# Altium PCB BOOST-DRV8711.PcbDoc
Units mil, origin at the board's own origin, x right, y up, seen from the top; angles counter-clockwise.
Board outline 2000 x 1750 mil, 2 copper layers (Top Layer, Bottom Layer), stack 64.8 mil thick; 30 components, 42 nets, 138 pads, 203 vias.
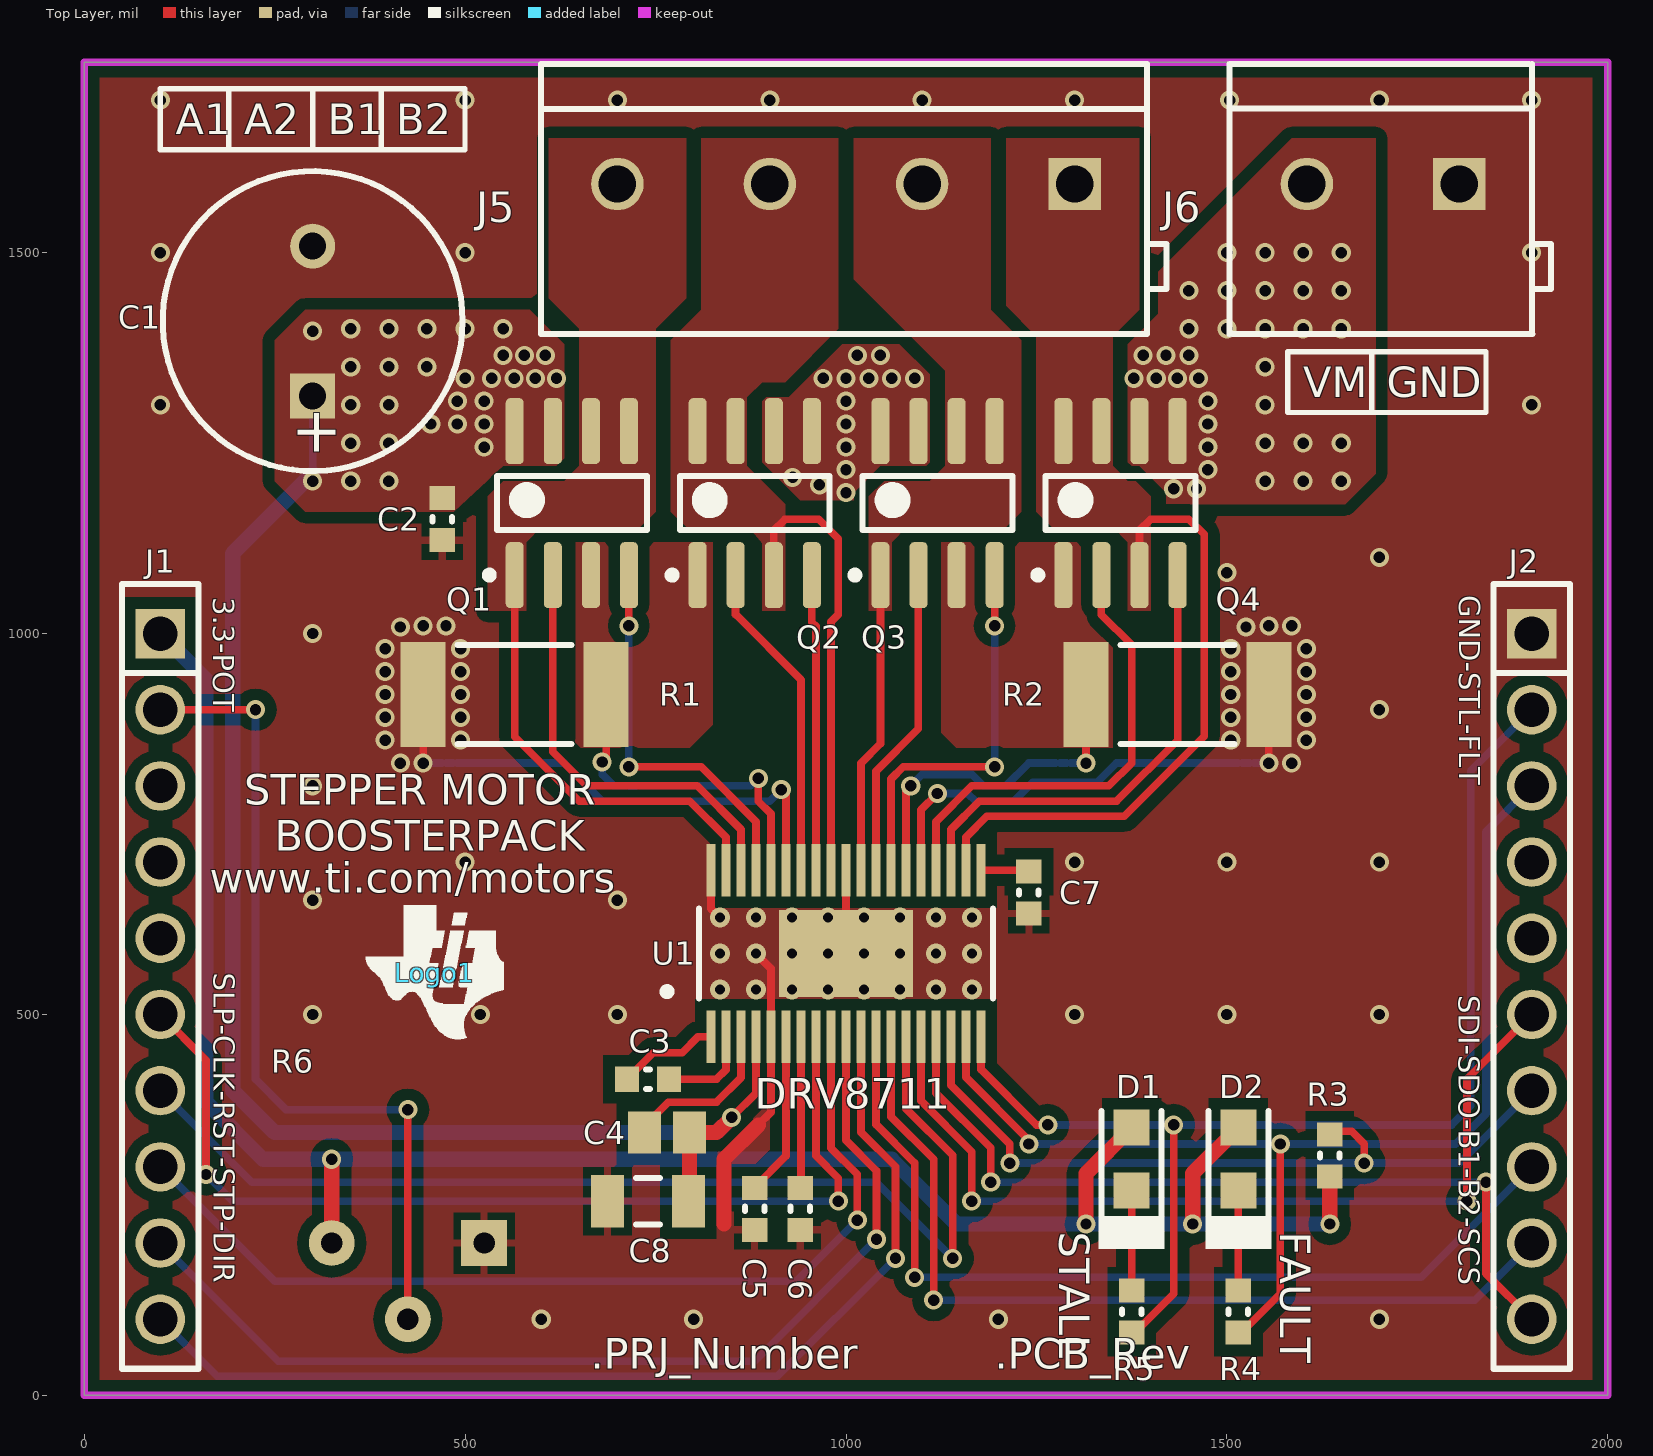
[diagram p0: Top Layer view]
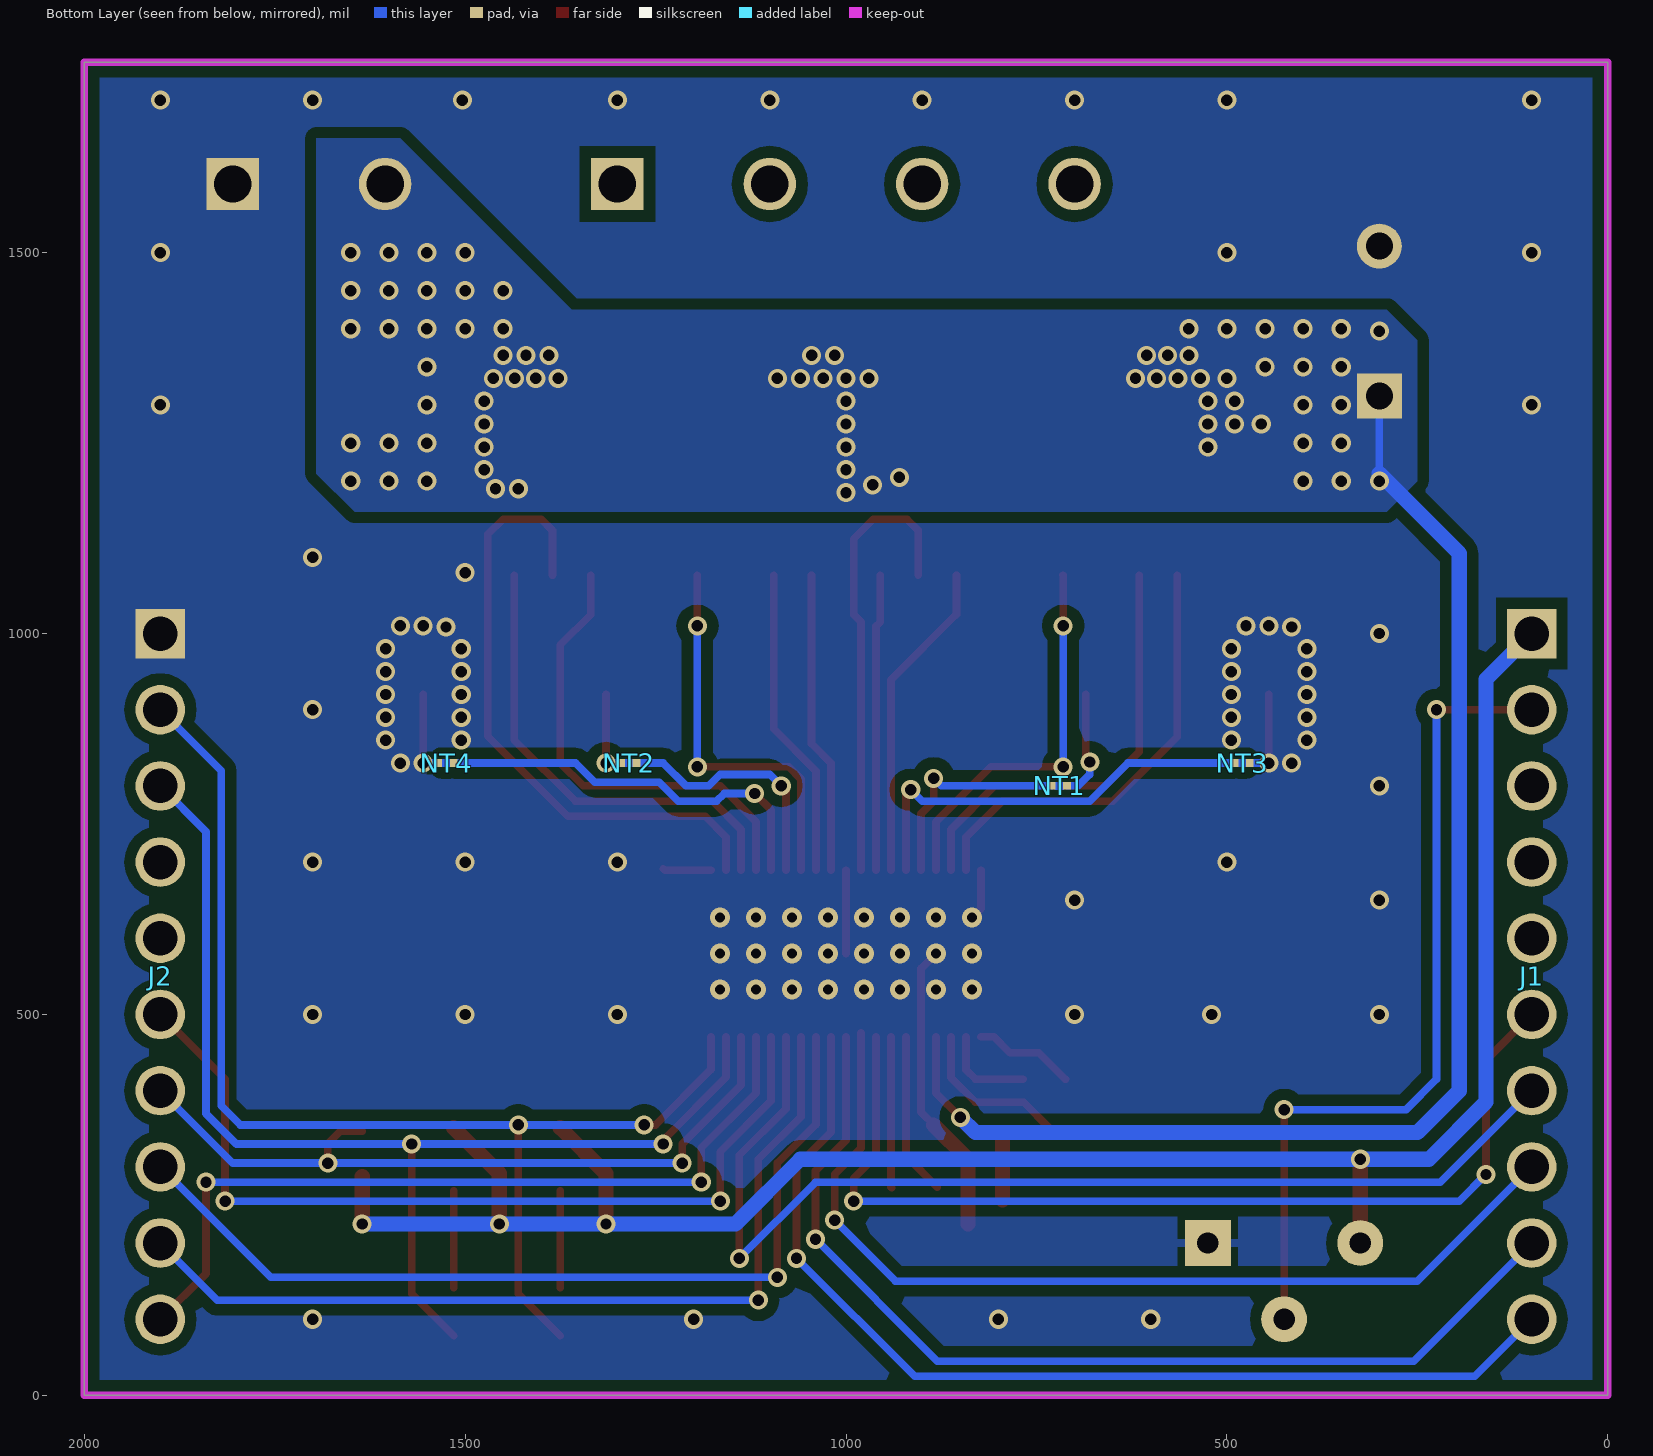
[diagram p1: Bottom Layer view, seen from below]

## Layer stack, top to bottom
Top Layer: signal copper 2.8
Dielectric: core 59.2, FR-4, Dk 4.8
Bottom Layer: signal copper 2.8

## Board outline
0,0 2000,0 2000,1750 0,1750

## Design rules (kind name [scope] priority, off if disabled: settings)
AcuteAngle [All] p1: minimum=4.50000000000000E+0001 checktracksonly=FALSE
AssemblyTestPointUsage [All] p1: valid=2
Clearance Clearance_BoardEdge_MountingHoles [OnCopper and InComponentClass('Mounting Holes') vs IsKeepOut] p1: gap=15
Clearance Clearance_BoardEdge_Poly [OnCopper and InPoly vs IsKeepOut] p2: gap=15
Clearance Clearance_BoardEdge [OnCopper and Not InComponentClass('Logo') and not InComponentClass('FiducialMark') and not InRegion(1000,500,4000,800) and Not IsKeepout vs IsKeepOut] p3: gap=15
Clearance Clearance_Poly [InPolygon] p4: gap=15
Clearance [All] p5: gap=7
ComponentClearance ComponentClearance_Logo [InComponentClass(Logo)] p1: gap=10 collisioncheckmode=3 verticalgap=10 showdistances=FALSE
ComponentClearance ComponentClearance_ScrewToNut [(HasFootprint('NY PMS 440 0025 PH')) vs (HasFootprint('Keystone_1902C'))] p2: gap=5 collisioncheckmode=3 verticalgap=10 showdistances=FALSE
ComponentClearance ComponentClearance_MountingHoles [InComponentClass('Mounting Holes')] p3: gap=250 collisioncheckmode=3 verticalgap=100000 showdistances=FALSE
ComponentClearance ComponentClearance_SmallPassives [HasFootprint('0201*') or HasFootprint('0402*') or HasFootprint('0508') or HasFootprint('0603*') or HasFootprint('0612') or HasFootprint('0805*') or HasFootprint('0815*') or HasFootprint('0830*') or HasFootprint('1206*') or HasFootprint('1210*') or HasFootprint('1808*') or HasFootprint('1812*') or HasFootprint('1825*') or HasFootprint('2010*') or HasFootprint('2220*') or HasFootprint('2225*') or HasFootprint('2512*') or HasFootprint('2728*') or HasFootprint('3518*') vs HasFootprint('0201*') or HasFootprint('0402*') or HasFootprint('0508') or HasFootprint('0603*') or HasFootprint('0612') or HasFootprint('0805*') or HasFootprint('0815*') or HasFootprint('0830*') or HasFootprint('1206*') or HasFootprint('1210*') or HasFootprint('1808*') or HasFootprint('1812*') or HasFootprint('1825*') or HasFootprint('2010*') or HasFootprint('2220*') or HasFootprint('2225*') or HasFootprint('2512*') or HasFootprint('2728*') or HasFootprint('3518*')] p4: gap=10 collisioncheckmode=3 verticalgap=10 showdistances=FALSE
ComponentClearance ComponentClearance_THtoSMT [IsThruComponent vs IsSMTComponent] p5: gap=10 collisioncheckmode=3 verticalgap=100000 showdistances=FALSE
ComponentClearance ComponentClearance_THtoTH [IsThruComponent vs IsThruComponent] p6: gap=0 collisioncheckmode=3 verticalgap=0 showdistances=FALSE
ComponentClearance [All] p7: gap=10 collisioncheckmode=3 verticalgap=10 showdistances=FALSE
DiffPairsRouting [All] p1: maxlimit=100 minlimit=10 mostfreqgap=10 maxuncoupledlength=1000
FabricationTestPointUsage TestPointUsage [All] p1: valid=2 allowmultiple=FALSE
FabricationTestpoint Testpoint [All] p1: side=3 testpointundercomponent=TRUE minsize=40 maxsize=100 preferedsize=60 minholesize=0 maxholesize=40 preferedholesize=32 testpointgrid=1 allowsidetop=TRUE allowsidebottom=TRUE usegrid=TRUE gridtolerance=0.01
FanoutControl Fanout_LCC [IsLCC] p1: bgadir=Out bgaviamode=Centered fanoutstyle=Auto fanoutdirection=Alternating viagrid=1 // Fanout_LCC (Default Rule)
FanoutControl Fanout_BGA [IsBGA] p2: bgadir=Out bgaviamode=Centered fanoutstyle=Auto fanoutdirection=Alternating viagrid=1 // Fanout_BGA (Default Rule)
FanoutControl Fanout_Default [All] p4: bgadir=Out bgaviamode=Centered fanoutstyle=Auto fanoutdirection=Alternating viagrid=1 // Fanout_Default (Default Rule)
FanoutControl Fanout_Small [(CompPinCount < 5)] p5: bgadir=Out bgaviamode=Centered fanoutstyle=Auto fanoutdirection=OutThenIn viagrid=1 // Fanout_Small (Default Rule)
HoleSize [All] p1: absolutevalues=TRUE maxlimit=251 minlimit=8 maxpercent=80.000 minpercent=20.000
MinimumAnnularRing [All] p1: minimumring=5
MinimumSolderMaskSliver MinimumSolderMaskSliver_Logo [InComponentClass('Logo') vs InComponentClass('Logo')] p1: minsoldermaskwidth=0.7
MinimumSolderMaskSliver [All] p2: minsoldermaskwidth=3
PlaneClearance [All] p1: clearance=15
PlaneConnect [All] p1: planeconnectstyle=Relief reliefexpansion=10 reliefentries=4 reliefconductorwidth=10 reliefairgap=10
PolygonConnect PolygonConnect_1 [IsNamedPolygon('GND_TOP') or IsNamedPolygon('GND_BOT') vs Not (InComponent('U1') or InComponent('J2') or InComponent('J3') or InComponent('J5') or InComponent('C1') or InComponent('R1') or InComponent('R2') or IsStitchingVia or IsVia)] p1: connectstyle=Relief reliefconductorwidth=10 reliefentries=4 polygonreliefangle="90 Angle" airgapwidth=10
PolygonConnect [All] p2: connectstyle=Direct reliefconductorwidth=10 reliefentries=4 polygonreliefangle="90 Angle" airgapwidth=10
RoutingVias [All] p1: holewidth=15 width=25 viastyle="Through Hole" minholewidth=8 minwidth=20 maxholewidth=40 maxwidth=65
SMDToCorner [All] p1: distance=30000
SilkToSilkClearance [All] p1: silktosilkclearance=5
SilkscreenOverComponentPads [All] p1: minsilkscreentomaskgap=5
SolderMaskExpansion [All] p1: expansion=3
Width [All] p1: maxlimit=100 minlimit=6 preferedwidth=10 checkconnectedcopper=TRUE
13 further rules are at their usual default settings.

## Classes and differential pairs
component class Logo: Logo1

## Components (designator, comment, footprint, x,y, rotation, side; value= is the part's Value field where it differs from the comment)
C1 "ECA-2AM101" CAPPR5-10X20 300,1410 r90 top
C2 "C1608X7R2A103K" 0603L 470,1150 r270 top
C3 "GRM188R72A104KA35D" 0603L 740,415 r0 top
C4 "CL21B105KBFNNNE" 0805L 765,345 r0 top
C5 "C1608X7R1E104K" 0603L 880,245 r270 top
C6 "C1608X7R1C105K" 0603L 940,245 r270 top
C7 "C0603C102K4RACTU" 0603L 1240,660 r270 top
C8 "HMK316B7105KL-T" 1206L 740,255 r180 top
D1 "LTST-C170KRKT" LED_LTST-C170 1375,310 r270 top
D2 "LTST-C170KRKT" LED_LTST-C170 1515,310 r270 top
J1 "CRD-081413-B-T" CONN_SSW-110-23-F-S 100,1000 r90 bottom
J2 "CRD-081413-B-T" CONN_SSW-110-23-F-S 1900,1000 r90 bottom
J5 "OSTTA024163" CONN_ED120-2DS 1705,1590 r90 top
J6 "OSTTA044163" CONN_ED120_4DS 1000,1590 r270 top
Logo1 "Texas Instruments" TI_Symbol_Overlay_Small 460,555 r0 top
NT1 "Net-Tie" Net-Tie_10mil 720,800 r180 bottom net-tie
NT2 "Net-Tie" Net-Tie_10mil 1285,830 r0 bottom net-tie
NT3 "Net-Tie" Net-Tie_10mil 480,830 r180 bottom net-tie
NT4 "Net-Tie" Net-Tie_10mil 1525,830 r0 bottom net-tie
Q1 "CSD88537ND" SO-8 640.23,1171.12 r90 top
Q2 "CSD88537ND" SO-8 880.23,1171.12 r90 top
Q3 "CSD88537ND" SO-8 1120.23,1171.12 r90 top
Q4 "CSD88537ND" SO-8 1360.23,1171.12 r90 top
R1 "CRA2512-FZ-R050ELF" 2512M 565,920 r0 top
R2 "CRA2512-FZ-R050ELF" 2512M 1435,920 r180 top
R3 "CRCW06033K30JNEA" 0603L 1635,315 r270 top
R4 "CRCW0603330RJNEA" 0603L 1515,110 r270 top
R5 "CRCW0603330RJNEA" 0603L 1375,110 r90 top
R6 "3386P-104TLF-ND" POT_3386P 425,200 r90 top
U1 "DRV8711DCP" R-PDSO-G38 1000,580 r90 top

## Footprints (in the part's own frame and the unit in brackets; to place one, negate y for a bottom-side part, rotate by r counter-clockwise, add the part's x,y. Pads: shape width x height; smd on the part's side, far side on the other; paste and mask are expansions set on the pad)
0603L [mm] "0603 from SM-752 data"
  rect 0.8x0.85 smd: 1(-0.7,0) 2(0.7,0)
  silkscreen extent -0.07,-0.33 0.07,0.33, body extent -0.87,-0.47 0.87,0.47, height 0.85
0805L [mm] "0805 from SM-752 data"
  rect 1.1x1.4 smd: 1(-0.75,0) 2(0.75,0)
  body extent -1.1,-0.72 1.1,0.72, height 1.1
1206L [mm] "1206 from SM-752 data"
  rect 1.1x1.75 smd: 1(-1.35,0) 2(1.35,0)
  silkscreen extent -0.4,-0.77 0.4,0.77, body extent -1.7,-0.9 1.7,0.9, height 1.35
2512M [mm] "Chip Resistor, Body 6.3x3.2mm, IPC Low Density"
  rect 1.5x3.5 smd: 1(-3.05,0) 2(3.05,0)
  silkscreen extent -1.9,-1.65 1.9,1.65, body extent -3.22,-1.67 3.22,1.67, height 0.71
CAPPR5-10X20 [mm] "Capacitor, Electrolytic, Radial; Body 10 x 20 mm (Dia.xH typ); Pin Spacing 5 mm (typ)"
  rect 1.5x1.5 hole 0.9: 1(-2.5,0)
  round 1.5 hole 0.9: 2(2.5,0)
  silkscreen extent -5,-5 5,5, body extent -5.01,-5.01 5.01,5.01, height 22
CONN_ED120-2DS [mm] "ONSHORE"
  rect 1.75x1.75 hole 1.25: 1(0,-2.54)
  round 1.75 hole 1.25: 2(0,2.54)
  silkscreen extent -5,-5.6 4,5.12, body extent -5,-5.6 4.15,5.12, height 13.1
CONN_ED120_4DS [mm] "ONSHORE"
  rect 1.75x1.75 hole 1.25: 1(0,7.62)
  round 1.75 hole 1.25: 2(0,2.54) 3(0,-2.54) 4(0,-7.62)
  silkscreen extent -4,-10.16 5,10.68, body extent -4.13,-10.01 5.05,10.68, height 13.1
CONN_SSW-110-23-F-S [mm] "SAMTEC"
  rect 1.65x1.65 hole 1.15: 1(0,0)
  round 1.65 hole 1.15: 2(-2.54,0) 3(-5.08,0) 4(-7.62,0) 5(-10.16,0) 6(-12.7,0) 7(-15.24,0) 8(-17.78,0) 9(-20.32,0) 10(-22.86,0)
  body extent -24.43,-1.27 1.57,1.27, height 8.59
LED_LTST-C170 [mm] "LITE-ON"
  rect 1.2x1.2 smd: 1(-1.05,0) 2(1.05,0)
  silkscreen extent -1.6,-1.1 3,1.1, body extent -1.05,-0.67 1.05,0.67, height 1.1
Net-Tie_10mil [mil] "10mil net tie, no solder mask opening, no solder paste"
  rect 10x10 smd paste-5 mask-5: 1(-10,0) 2(10,0)
  Top Layer region: -6,5 6,5 6,-5 -6,-5
POT_3386P [mil]
  rect 60x60 hole 28: 1(0,-100)
  round 60 hole 28: 2(-100,0) 3(0,100)
R-PDSO-G38 [mm] "PowerPAD Plastic Small-Outline Package"
  rect 2.9x4.48 smd: 0(0,0)
  rect 1.75x0.3 smd mask+0.05: 1(-2.775,4.5) 2(-2.775,4) 3(-2.775,3.5) 4(-2.775,3) 5(-2.775,2.5) 6(-2.775,2) 7(-2.775,1.5) 8(-2.775,1) 9(-2.775,0.5) 10(-2.775,0) 11(-2.775,-0.5) 12(-2.775,-1) 13(-2.775,-1.5) 14(-2.775,-2) 15(-2.775,-2.5) 16(-2.775,-3) 17(-2.775,-3.5) 18(-2.775,-4) 19(-2.775,-4.5) 20(2.775,-4.5) 21(2.775,-4) 22(2.775,-3.5) 23(2.775,-3) 24(2.775,-2.5) 25(2.775,-2) 26(2.775,-1.5) 27(2.775,-1) 28(2.775,-0.5) 29(2.775,0) 30(2.775,0.5) 31(2.775,1) 32(2.775,1.5) 33(2.775,2) 34(2.775,2.5) 35(2.775,3) 36(2.775,3.5) 37(2.775,4) 38(2.775,4.5)
  silkscreen extent -1.5,-4.9 1.5,6.09, body extent -2.25,-4.9 2.25,4.9, height 1.2
SO-8 [mm] "SOIC, 8-Leads, Body 5.0x4.0mm (max), Pitch 1.27mm, IPC Medium Density"
  rrect50% 2.2x0.6 smd: 1(-2.4,1.905) 2(-2.4,0.635) 3(-2.4,-0.635) 4(-2.4,-1.905) 5(2.4,-1.905) 6(2.4,-0.635) 7(2.4,0.635) 8(2.4,1.905)
  silkscreen extent -2.52,-2.5 0.9,2.88, body extent -3,-2.45 3,2.45, height 1.59
TI_Symbol_Overlay_Small [mil]
  silkscreen extent -90,-88 91,88

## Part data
C1: library part EEV-FK2A101M, "CAP ALUM 100UF 100V 20% RADIAL"
C2: "CAP, CERM, 0.01uF, 100V, +/-10%, X7R, 0603"
C3: "CAP, CERM, 0.1uF, 100V, +/-10%, X7R, 0603"
C4: library part GRM21BR71H105KA12L, "CAP CER 1UF 50V 10% X7R 0805"
C5: "CAP, CERM, 0.1uF, 25V, +/-10%, X7R, 0603"
C6: "CAP, CERM, 1uF, 16V, +/-10%, X7R, 0603"
C7: library part GRM188R71C102KA01D, "CAP, CERM, 1000pF, 16V, +/-10%, X7R, 0603"
C8: library part GRM31CR72A105KA01L, "CAP CER 1UF 100V 10% X7R 1206"
D1 D2: "LED, Red, SMD"
J1 J2: library part SSW-110-23-F-S, "Connector, Receptacle, 100mil, 10x1, Gold plated, TH"
J5: library part ED120/2DS, "TERMINAL BLOCK 5.08MM VERT 2POS, TH"
J6: library part ED120/4DS, "Terminal Block, 4x1, 5.08mm, TH"
Logo1: library part TI_Logo, "Texas Instrument Corporate Signature"
NT1 NT2 NT3 NT4: "Single point connection between nets."
Q1 Q2 Q3 Q4: "Dual 60-V N-Channel NexFET™ Power MOSFETs"
R1 R2: "RES, 0.05 ohm, 1%, 3W, 2512"
R3: "RES, 3.3k ohm, 5%, 0.1W, 0603"
R4 R5: "RES, 330 ohm, 5%, 0.1W, 0603"
R6: library part POT_3386P, "TRIMMER 100K OHM 0.5W PC PIN"
U1: "Stepper Motor Pre-Driver with On-Chip 1/256 Micro-Stepping Indexer and Stall Detect"

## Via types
v1: diameter 25, hole 15, Top Layer to Bottom Layer, tented both sides, 179 vias
v2: diameter 26, hole 13, Top Layer to Bottom Layer, tented top, 24 vias

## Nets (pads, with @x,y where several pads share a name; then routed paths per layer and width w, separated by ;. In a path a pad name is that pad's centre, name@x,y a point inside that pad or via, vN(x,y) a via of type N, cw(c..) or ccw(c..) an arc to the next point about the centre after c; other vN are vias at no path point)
3.3V: D1.1 D2.1 J1.1 R3.2 R6.3 | length 2656
  Top Layer w20: R6.3 v1(325,310) ; v1(1315,225) 1315,291.34 D1.1 ; v1(1455,225) 1455,291.34 D2.1 ; v1(1635,225) R3.2
  Bottom Layer w20: J1.1 160,940 160,385 235,310 1060,310 1145,225 v1(1455,225) v1(1635,225)
A1HS: Q1.2 U1.36 | length 574.5
  Top Layer w10: Q1.2@615,1076.4 615,845 660,800 805,800 862.2,742.8 U1.36
A1LS: Q1.4 U1.35 | length 512.3
  Top Layer w10: v1(715,825) 810,825 881.89,753.11 U1.35 ; v1(715,1010) 715,1076.4 Q1.4
  Bottom Layer w10: v1(715,825) v1(715,1010)
A2HS: Q2.4 U1.31 | length 389.6
  Top Layer w10: Q2.4 955.23,1014.77 960.63,1009.37 U1.31
A2LS: Q2.2 U1.32 | length 422.8
  Top Layer w10: Q2.2@855,1076.4 855,1025 940.94,939.06 U1.32
AISENN: NT3.1 U1.33 | length 560.3
  Top Layer w10: v1(915,795) 921.26,788.74 U1.33
  Bottom Layer w10: NT3.1 630,830 680,780 900,780 v1(915,795)
AISENP: NT1.1 U1.34 | length 286.8
  Top Layer w10: v1(885,810) 885,780 901.57,763.43 U1.34
  Bottom Layer w10: NT1.1 875,800 v1(885,810)
AOUT1: J6.4 Q1.1 Q1.5 Q1.6 U1.37 | length 587.2
  Top Layer w10: Q1.1 565.23,864.77 650,780 795,780 842.52,732.48 U1.37
AOUT2: J6.3 Q2.3 Q2.7 Q2.8 U1.30 | length 599.2
  Top Layer w10: Q2.3 905.23,1135.23 920,1150 964.34,1150 990,1124.34 990,1024.99 980.31,1015.3 U1.30
B1HS: Q3.2 U1.27 | length 410.2
  Top Layer w10: U1.27 1039.37,819.37 1095,875 Q3.2@1095,1076.4
B1LS: Q3.4 U1.26 | length 514.1
  Top Layer w10: U1.26 1059.06,809.06 1075,825 v1(1195,825) ; v1(1195,1010) 1195,1076.4 Q3.4
  Bottom Layer w10: v1(1195,825) v1(1195,1010)
B2HS: Q4.4 U1.22 | length 616
  Top Layer w10: U1.22 1137.8,742.8 1175,780 1355,780 1435.23,860.23 Q4.4
B2LS: Q4.2 U1.23 | length 615.7
  Top Layer w10: U1.23 1118.11,753.11 1165,800 1345,800 1375,830 1375,985 1335.23,1024.77 Q4.2
BEMF: C7.1 U1.20 | length 63.8
  Top Layer w10: U1.20 1237.76,689.25 C7.1@1240,691.5
BIN1: J2.8 U1.12 | length 1206.8
  Top Layer w10: U1.12 1039.37,355.63 1090,305 v1(1090,155)
  Bottom Layer w10: v1(1090,155) 1755,155 J2.8
BIN2: J2.9 U1.13 | length 1185
  Top Layer w10: U1.13 1059.06,365.94 1115,310 v1(1115,125)
  Bottom Layer w10: v1(1115,125) 1825,125 J2.9
BISENN: NT4.1 U1.24 | length 529.5
  Top Layer w10: U1.24 1098.43,768.43 v1(1120,790)
  Bottom Layer w10: v1(1120,790) 1160,790 1170,780 1220,780 1245,805 1330,805 1355,830 NT4.1
BISENP: NT2.1 U1.25 | length 328.2
  Top Layer w10: U1.25 1078.74,793.74 v1(1085,800)
  Bottom Layer w10: v1(1085,800) 1100,815 1165,815 1180,800 1210,800 1240,830 NT2.1
BOUT1: J6.2 Q3.1 Q3.5 Q3.6 U1.28 | length 398
  Top Layer w10: U1.28 1019.68,829.68 1045.23,855.23 Q3.1
BOUT2: J6.1 Q4.3 Q4.7 Q4.8 U1.21 | length 833.4
  Top Layer w10: U1.21 1157.48,732.48 1185,760 1365,760 1470,865 1470,1130 1450,1150 1400,1150 1385.23,1135.23 Q4.3
CP1: C3.1 U1.1 | length 134
  Top Layer w10: C3.1@711.95,415 746.95,450 785,450 805.75,470.75 U1.1
CP2: C3.2 U1.2 | length 123.4
  Top Layer w10: C3.2 830,415 842.52,427.52 U1.2
DIR/AIN2: J1.10 U1.11 | length 1369.8
  Top Layer w10: U1.11 1019.68,345.32 1065,300 v1(1065,180)
  Bottom Layer w10: J1.10 175,25 910,25 v1(1065,180)
GND: C1.2 C2.2 C5.2 C6.2 C7.2 C8.2 J2.1 J5.1 NT3.2 NT4.2 R1.1 R2.1 R6.1 U1.0 U1.5 U1.29 U1.38 | length 789.9
  Top Layer w10: R1.1 445,919.92 v1(445,830) ; U1.38 822.83,639.06 v2(834.65,627.24) ; v2(881.89,580) 901.57,560.31 U1.5 901.57,371.57 885,355 ; U1.0 U1.29 ; v1(1555,830) 1555,919.92 R2.1
  Top Layer w20: 840,225 840,310 885,355
  Bottom Layer w10: v1(445,830) NT3.2 ; NT4.2 v1(1555,830)
  other v1: 600,100 800,100 1200,100 1700,100 300,500 520,500 700,500 1300,500 1500,500 1700,500 300,650 700,650 500,700 1300,700 1500,700 1700,700 300,800 415,830 1585,830 395,860 494.29,860 1505,860 1604.29,860 395,890 494.29,890 1505,890 1604.29,890 1700,900 395,920 494.29,920 1505,920 1604.29,920 395,950 494.29,950 1505,950 1604.29,950 395,980 494.29,980 1505,980 1604.29,980 300,1000 415,1008.58 1525,1008.58 445,1010 475,1010 1555,1010 1585,1010 1500,1080 1700,1100 100,1300 1900,1300 100,1500 500,1500 1900,1500 100,1700 500,1700 700,1700 900,1700 1100,1700 1300,1700 1503.62,1700 1700,1700 1900,1700
  other v2: 834.65,532.76 881.89,532.76 929.13,532.76 976.38,532.76 1023.62,532.76 1070.87,532.76 1118.11,532.76 1165.35,532.76 834.65,580 929.13,580 976.38,580 1023.62,580 1070.87,580 1118.11,580 1165.35,580 881.89,627.24 929.13,627.24 976.38,627.24 1023.62,627.24 1070.87,627.24 1118.11,627.24 1165.35,627.24
GND_A: NT1.2 Q1.3 Q2.1 R1.2 | length 143.3
  Top Layer w10: v1(680,831.42) 685.08,836.5 R1.2
  Bottom Layer w10: v1(680,831.42) 680,815 695,800 NT1.2
GND_B: NT2.2 Q3.3 Q4.1 R2.2 | length 110
  Top Layer w10: R2.2 1315,919.92 v1(1315,830)
  Bottom Layer w10: NT2.2 v1(1315,830)
NetD1_2: D1.2 R5.2 | length 127.2
  Top Layer w10: R5.2@1375,141.5 D1.2
NetD2_2: D2.2 R4.1 | length 127.2
  Top Layer w10: R4.1@1515,141.5 D2.2
NFAULT: J2.3 R4.2 U1.18 | length 1520.6
  Top Layer w10: U1.18 1157.48,417.52 1240,335 v1(1240,330) ; R4.2@1515,78.5 1570,133.5 v1(1570,330)
  Bottom Layer w10: v1(1240,330) 1800,330 1840,370 1840,740 J2.3
NSLEEP: J1.6 U1.8 | length 1307.3
  Top Layer w10: J1.6 160,440 v1(160,290) ; U1.8 960.63,314.37 990,285 v1(990,255)
  Bottom Layer w10: v1(160,290) 195,255 v1(990,255)
NSTALL: J2.2 R5.1 U1.19 | length 1578.7
  Top Layer w10: U1.19 1177.17,427.83 1250,355 v1(1265,355) ; R5.1@1375,78.5 1430,133.5 v1(1430,355)
  Bottom Layer w10: v1(1265,355) 1795,355 1820,380 1820,820 J2.2
POT: J1.2 R6.2 | length 1101.6
  Top Layer w10: J1.2 v1(225,900) ; R6.2 v1(425,375)
  Bottom Layer w10: v1(225,900) 225,415 265,375 v1(425,375)
RESET: J1.8 U1.9 | length 1270.4
  Top Layer w10: U1.9@980.31,475.75 980.31,324.69 1015,290 v1(1015,230)
  Bottom Layer w10: J1.8 250,150 935,150 v1(1015,230)
SCLK: J1.7 U1.14 | length 1447.2
  Top Layer w10: U1.14 1078.74,376.26 1140,315 v1(1140,180)
  Bottom Layer w10: J1.7 220,280 1040,280 v1(1140,180)
SCS: J2.10 U1.16 | length 1070.4
  Top Layer w10: U1.16 1118.11,396.89 1190,325 v1@1190,285 ; v1(1840,280) 1840,160 J2.10
  Bottom Layer w10: v1(1190,280) v1(1840,280)
SDATI: J2.6 U1.15 | length 1173.5
  Top Layer w10: U1.15 1098.43,386.57 1165,320 v1(1165,255) ; v1(1815,255) 1815,415 J2.6
  Bottom Layer w10: v1(1165,255) v1(1815,255)
SDATO: J2.7 R3.1 U1.17 | length 988.9
  Top Layer w10: U1.17 1137.8,407.2 1215,330 v1@1215,315 ; R3.1@1635,346.5 1663.5,346.5 1680,330 v1(1680,305)
  Bottom Layer w10: v1(1215,305) v1(1680,305) 1805,305 J2.7
STEP/AIN1: J1.9 U1.10 | length 1352.8
  Top Layer w10: U1.10 1000,335 1040,295 v1(1040,205)
  Bottom Layer w10: J1.9 255,45 880,45 v1(1040,205)
V5: C5.1 U1.6 | length 214.8
  Top Layer w10: C5.1@880,273.05 921.26,314.31 U1.6
VCP: C4.1 U1.3 | length 210.2
  Top Layer w10: C4.1@733,351 767,385 830,385 862.2,417.2 U1.3
VINT: C6.1 U1.7 | length 198.6
  Top Layer w10: C6.1 940.94,273.5 U1.7
VM: C1.1 C2.1 C4.2 C8.1 J5.2 Q1.7 Q1.8 Q2.5 Q2.6 Q3.7 Q3.8 Q4.5 Q4.6 U1.4 | length 1912.5
  Top Layer w10: v1(850,365) 881.89,396.89 U1.4
  Top Layer w20: C8.1@794.53,256.38 C4.2 830,345 v1(850,365)
  Bottom Layer w10: v1@300,1210 C1.1
  Bottom Layer w20: v1@300,1210 195,1105 195,400 250,345 830,345 v1(850,365)
  other v1: 1000,1185 1430,1190 1460,1190 965,1195 300,1200 350,1200 400,1200 1550,1200 1600,1200 1650,1200 930,1205 1000,1215 1475,1215 525,1244.53 1000,1244.53 1475,1244.53 350,1250 400,1250 1550,1250 1600,1250 1650,1250 455,1275 490,1275 525,1275 1000,1275 1475,1275 350,1300 400,1300 1550,1300 490,1305 525,1305 1000,1305 1475,1305 500,1335 535,1335 564.44,1335 592.22,1335 620,1335 970,1335 1000,1335 1030,1335 1060,1335 1090,1335 1377.78,1335 1407.22,1335 1435,1335 1462.78,1335 350,1350 400,1350 450,1350 1550,1350 550,1365 577.74,1365 605.47,1365 1015,1365 1045,1365 1390,1365 1420,1365 1450,1365 300,1396.78 350,1400 400,1400 450,1400 500,1400 550,1400 1450,1400 1500,1400 1550,1400 1600,1400 1650,1400 1450,1450 1500,1450 1550,1450 1600,1450 1650,1450 1500,1500 1550,1500 1600,1500 1650,1500
pads on no net: J1.3 J1.4 J1.5 J2.4 J2.5

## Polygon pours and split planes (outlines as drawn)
VM on Top Layer "VM_TOP3" (solid, remove dead copper, pour order 24): 1370,1380 1410,1420 1410,1475 1585,1650 1695,1650 1695,1210 1655,1170 1420,1170 1420,1185 1385,1220 1375,1220 1370,1225
VM on Top Layer "VM_TOP1" (solid, remove dead copper, pour order 22): 630,1380 630,1230 620,1220 550,1220 485,1160 290,1160 250,1200 250,1385 290,1425 585,1425
BOUT2 on Top Layer "BOUT2" (solid, remove dead copper, pour order 20): 1250,1160 1270,1140 1350,1140 1370,1120 1370,1030 1400,1030 1400,1180 1380,1200 1370,1200 1350,1220 1350,1390 1385,1425 1385,1650 1210,1650 1210,1430 1250,1390
AOUT1 on Top Layer "AOUT1" (solid, remove dead copper, pour order 17): 600,1140 580,1120 580,1030 530,1030 530,1180 550,1200 630,1200 650,1220 650,1400 610,1440 610,1650 790,1650 790,1440 750,1400 750,1160 730,1140
AOUT2 on Top Layer "AOUT2" (solid, remove dead copper, pour order 18): 770,1160 790,1140 870,1140 880,1130 890,1118.58 890,1030 920,1030 920,1170 870,1220 870,1310 890,1330 920,1330 990,1400 990,1650 810,1650 810,1425 770,1385
VM on Top Layer "VM_TOP2" (solid, remove dead copper, pour order 23): 890,1225 890,1305 895,1310 925,1310 995,1380 1070,1380 1110,1340 1110,1225 1105,1220 1045,1220 1010,1185 1010,1175 940,1175
GND_A on Top Layer "GND_A" (solid, remove dead copper, pour order 12): 645,1120 825,1120 825,880 795,850 644.84,850 645,865
GND_B on Top Layer "GND_B" (solid, remove dead copper, pour order 14): 1305,1120 1125,1120 1125,870 1145,850 1350,850 1350,1120
BOUT1 on Top Layer "BOUT1" (solid, remove dead copper, pour order 19): 1080,1140 1210,1140 1230,1160 1230,1385 1190,1425 1190,1650 1010,1650 1010,1465 1130,1345 1130,1220 1110,1200 1050,1200 1030,1180 1030,1030 1059.92,1030 1060,1120
GND on Top Layer "GND_TOP" (solid, remove dead copper, pour order 32): 0,1750 2000,1750 2000,0 0,0
VM on Bottom Layer "VM_BOT" (solid, remove dead copper, pour order 21): 290,1425 250,1385 250,1200 290,1160 1645,1160 1695,1210 1695,1650 1585,1650 1360,1425
GND on Bottom Layer "GND_BOT" (solid, remove dead copper, pour order 31): 0,1750 2000,1750 2000,0 0,0

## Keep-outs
Keep-Out Layer:
  the board outline again, w10
  text ".Layer_Name" at 577,-858.49 h60

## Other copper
Top Layer:
  text ".Layer_Name" at 577,-858.49 h60
Bottom Layer:
  text ".Layer_Name" at 577,-858.49 h60

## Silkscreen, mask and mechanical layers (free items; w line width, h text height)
Top Overlay:
  lines w7: 190,1635 190,1715 ; 300,1635 300,1715 ; 390,1635 390,1715 ; 1690,1290 1690,1370 ; 100,1635 500,1635 500,1715 100,1715 100,1635 ; 1580,1290 1840,1290 1840,1370 1580,1370 1580,1290
  text "A1" at 120,1655 h40
  text "A2" at 210,1655 h40
  text "B1" at 320,1655 h40
  text "B2" at 410,1655 h40
  text "VM" at 1600,1310 h40
  text "GND" at 1710,1310 h40
  text "GND-STL-FLT" at 1805,1050 h28 r270
  text "3.3-POT" at 169.51,1047.48 h28 r270
  text "STEPPER MOTOR" at 210,775 h40
  text "BOOSTERPACK" at 250,715 h40
  text "www.ti.com/motors" at 165,660 h40
  text "SLP-CLK-RST-STP-DIR" at 170,555 h28 r270
  text "SDI-SDO-B1-B2-SCS" at 1804.24,525.32 h28 r270
  text "DRV8711" at 880,376.46 h40
  text "STALL" at 1280,215 h40 r270
  text "FAULT" at 1570,215 h40 r270
  text ".PRJ_Number" at 665,35 h40
  text ".PCB_Rev" at 1195,35 h40
  text ".Layer_Name" at 577,-858.49 h60
Bottom Overlay:
  text ".Layer_Name" at 577,-858.49 h60
Top Paste:
  text ".Layer_Name" at 577,-858.49 h60
Bottom Paste:
  text ".Layer_Name" at 577,-858.49 h60
Top Solder:
  text ".Layer_Name" at 577,-858.49 h60
  text ".Layer_Name" at 577,-858.49 h60
Bottom Solder:
  text ".Layer_Name" at 577,-858.49 h60
Drill Guide:
  text ".Layer_Name" at 577,-858.49 h60
M1 Board Outline:
  the board outline again, w10
  text ".Layer_Name" at 577,-858.49 h60
M2 Board Dimensions:
  rectangle: -0.5,-285.5 124.5,-160.5
  rectangle: 124.5,-410.5 499.5,-285.5
  lines w7: -0.5,-285.5 999.5,-285.5 ; 124.5,-410.5 124.5,-160.5 ; 249.5,-410.5 249.5,-160.5 ; 499.5,-410.5 499.5,-160.5 ; 749.5,-410.5 749.5,-160.5 ; -0.5,-410.5 999.5,-410.5 999.5,-160.5 -0.5,-160.5 -0.5,-410.5
  lines w10: -0.5,-475.5 -0.5,-455.5 ; 59.5,-485.5 -0.5,-465.5 ; 59.5,-445.5 -0.5,-465.5 ; 223.58,-465.5 -0.5,-465.5 ; 775.42,-465.5 999.5,-465.5 ; 939.5,-485.5 999.5,-465.5 ; 939.5,-445.5 999.5,-465.5 ; 999.5,-475.5 999.5,-455.5
  text "1000 (mil)" at 233.58,-501.49 h60
  text ".Layer_Name" at 577,-858.49 h60
M3 3D STEP Top:
  text ".Layer_Name" at 577,-858.49 h60
M4 3D STEP Bottom:
  text ".Layer_Name" at 577,-858.49 h60
M5 Assembly Top:
  lines w7: 2319,170.5 3444,170.5 ; 2319,293 3441.5,293 ; 2634,50.5 2634,413 ; 3019,50.5 2319,50.5 ; 3019,413 2319,413 ; 2319,50.5 3444,50.5 3444,413 2319,413 ; 2319,50.5 2319,413
  lines w10: -292,-930.17 6308,-930.17 ; -292,-726.83 6310,-726.83 ; -292,-523.5 -292,-1133.5 3713,-1133.5 6310,-1133.5 6310,-523.5 -291.5,-523.5 -291.5,-1133.5 1284,-1133.5 ; 2173,-1133.5 2173,-523.5 ; 3440,-726.83 3440,-523.5 ; 4280,-726.83 4280,-523.5 ; 4902,-1140 4902,-937.17
  text "TABLE 1" at 2706.5,448 h40
  text "Variant" at 2344,338 h40
  text "Label text" at 2779,338 h40
  text "001" at 2411.5,218 h40
  text "ChangeMe!" at 2689,215.5 h40
  text "002" at 2411.5,93 h40
  text "ChangeMe!" at 2684,90.5 h40
  text "COMPONENTS MARKED 'DNP' SHOULD NOT BE POPULATED." at 1153.5,-318.5 h60
  text "ASSEMBLY VARIANT:" at 1153,-434 h60
  text ".VariantName" at 2189,-434 h60
  text "PCB VIEWED FROM TOP SIDE" at -228.5,-655.67 h60
  text "BOARD #:" at 2248,-655.67 h60
  text ".PRJ_Number" at 2793.5,-655.67 h60
  text "REV:" at 3638,-655.67 h60
  text ".PCB_Rev" at 3929.5,-655.67 h60
  text "SVN REV:" at 4476,-655.67 h60
  text ".VersionControl_RevNumber" at 4982,-655.67 h60
  text "IGNORE ->" at -228.5,-858.49 h60
  text "PLOT NAME =" at -228.5,-1064.34 h60
  text ".plot_File_Name" at 577,-1064.34 h60
  text "GENERATED    :" at 2250,-1064.34 h60
  text ".Print_Date" at 3119.5,-1064.34 h60
  text ".Print_Time" at 3848.5,-1064.34 h60
  text "TEXAS INSTRUMENTS" at 5113,-1064.34 h60
M6 Assembly Bottom:
  lines w10: -292.5,-727.33 6309.5,-727.33 ; -290.5,-930.67 6309.5,-930.67 ; 1115.5,-1140.5 1115.5,-937.67 ; 1737.5,-727.33 1737.5,-524 ; 2577.5,-727.33 2577.5,-524 ; 3844.5,-1134 3844.5,-524 ; 4733.5,-1134 6309,-1134 6309,-524 -292.5,-524 -292.5,-1134 2304.5,-1134 6309.5,-1134 6309.5,-524
  text "COMPONENTS MARKED 'DNP' SHOULD NOT BE POPULATED." at 6102,-318 h60
  text ".VariantName" at 5058,-434 h60
  text "ASSEMBLY VARIANT:" at 6097,-434 h60
  text ".VersionControl_RevNumber" at 1035.5,-656.17 h60
  text "SVN REV:" at 1541.5,-656.17 h60
  text ".PCB_Rev" at 2088,-656.17 h60
  text "REV:" at 2379.5,-656.17 h60
  text ".PRJ_Number" at 3224,-656.17 h60
  text "BOARD #:" at 3769.5,-656.17 h60
  text "PCB VIEWED FROM BOTTOM SIDE" at 6246,-656.17 h60
  text "IGNORE ->" at 2547.85,-858.49 h60
  text "TEXAS INSTRUMENTS" at 904.5,-1064.84 h60
  text ".Print_Time" at 2169,-1064.84 h60
  text ".Print_Date" at 2898,-1064.84 h60
  text "GENERATED    :" at 3767.5,-1064.84 h60
  text ".plot_File_Name" at 5440.5,-1064.84 h60
  text "PLOT NAME =" at 6246,-1064.84 h60
M9 Title Sheet:
  drawing of 57 lines, arcs and shapes, not listed
  text "1" at 739.84,8036.5 h70
  text "2" at 3235.5,8036.5 h70
  text "3" at 5724.84,8036.5 h70
  text "4" at 8231.51,8036.5 h70
  text "5" at 10730.5,8036.5 h70
  text "6" at 13235.5,8036.5 h70
  text "A" at -416.5,6893.5 h70
  text "A" at 14383.5,6893.5 h70
  text "B" at -416.5,4513.5 h70
  text "B" at 14383.5,4513.5 h70
  text "C" at -416.5,2138.5 h70
  text "C" at 14383.5,2138.5 h70
  text "PROJECT TITLE:" at 11343.5,277.5 h45
  text ".PRJ_Title" at 11393.5,144.17 h70
  text "DESIGNED FOR:" at 11343.5,-23.5 h45
  text ".PRJ_Customer" at 11393.5,-163.5 h70
  text "D" at -416.5,-231.5 h70
  text "D" at 14383.5,-231.5 h70
  text "FILE NAME:" at 11343.5,-323.5 h45
  text ".PCB_File_Name_No_Path" at 11393.5,-443.5 h70
  text "Texas Instruments (TI) and/or its licensors do not warrant the accuracy or completeness of this specification" at 6374,-605.34 h45
  text "ENGINEER:" at 11343.5,-613.5 h45
  text "LAYOUT BY:" at 12848.5,-613.5 h45
  text "or any information contained therein. TI and/or its licensors do not warrant that this design will meet" at 6329.01,-718 h45
  text ".PRJ_Engineer" at 11393.5,-768.49 h70
  text ".PCB_Layout" at 12899,-768.49 h70
  text "the specifications, will be suitable for your application or fit for any particular purpose, or will operate in" at 6329.01,-830.67 h45
  text ".Layer_Name" at 577,-858.49 h60
  text "ALTIUM DESIGNER VERSION:" at 12848.5,-923.5 h45
  text "an implementation. TI and/or its licensors do not warrant that the design is production worthy. You should" at 6329.01,-943.33 h45
  text "completely validate and test your design implementation to confirm the system functionality for your application." at 6374,-1056 h45
  text ".print_Scale" at 11393.5,-1056.83 h70
  text ".Application_BuildNumber" at 12899,-1056.83 h70
  text "1" at 739.84,-1263.5 h70
  text "2" at 3235.5,-1263.5 h70
  text "3" at 5724.84,-1263.5 h70
  text "4" at 8231.51,-1263.5 h70
  text "5" at 10730.5,-1263.5 h70
  text "6" at 13235.5,-1263.5 h70
M10 Fab Notes:
  drawing of 212 lines, arcs and shapes, not listed
  text "DESIGN INFORMATION" at 12381.02,6810 h60
  text "(REFER ALSO ARRAY/PANEL PROFILING INFORMATION)" at 12019.46,6648.29 h60
  text "BOARD SIZE" at 11333.46,6644 h60
  text "2000MIL" at 11795.78,6516.18 h60
  text "X" at 12301.46,6516.18 h60
  text "1750MIL" at 12532.78,6516.18 h60
  text "Number of Layers :" at 11736.46,6319 h60
  text "2" at 12831.27,6309 h60
  text "MIN. TRACK WIDTH:" at 11736.46,6180 h60
  text "8" at 12832.7,6180 h60
  text "MIL" at 12987.46,6180 h60
  text "MIN. CLEARANCE:" at 11736.46,6048 h60
  text "8" at 12832.7,6048 h60
  text "MIL" at 12987.46,6048 h60
  text "MIN. VIA PAD SIZE:" at 11736.46,5916 h60
  text "24" at 12802.71,5916 h60
  text "MIL" at 12987.46,5916 h60
  text "0.05mm (2MIL)" at 12431.46,5774.29 h60
  text "MINIMUM ANNULAR RING" at 11407.23,5770 h60
  text "EXTERNAL" at 13139.46,5770 h60
  text "PER" at 11607.23,5652 h60
  text "IPC-D-275 CLASS 2 LEVEL C" at 11827.23,5652 h60
  text "MIL, HOLES" at 13315.46,5539.71 h60
  text "+/-" at 12923,5539 h60
  text "+/-" at 13777,5539 h60
  text "REGISTRATION TOLERANCES:" at 11407.23,5534 h60
  text "METAL" at 12607,5534 h60
  text "5" at 13183.2,5534 h60
  text "3" at 14016.2,5534 h60
  text "MIL" at 14132.46,5534 h60
  text "MATERIAL:" at 11332.46,5324.54 h60
  text "FR-4 High Tg" at 12318.9,5184.21 h60
  text "FR-408" at 11753.46,5175.64 h60
  text "X" at 12165.46,5175.64 h60
  text "OTHER" at 13241.46,5175.64 h60
  text "62 MIL (1.6mm) +/-10%" at 12073.56,5012.92 h60
  text "THICKNESS:" at 11407.23,5008.64 h60
  text "X" at 11945.4,5008.64 h60
  text "OTHER" at 13358.46,5008.64 h60
  text "TOLERANCE:" at 11407.23,4850.64 h60
  text "X" at 12246.53,4850.64 h60
  text "ANSI IPC-6012 TYPE 3 CLASS 2" at 12433.48,4850.64 h60
  text "OTHER +/-" at 12433.46,4694.64 h60
  text "BOW & TWIST:" at 11407.23,4537.64 h60
  text "X" at 12246.53,4537.64 h60
  text "ANSI IPC-6012 TYPE 3 CLASS 2" at 12433.48,4537.64 h60
  text "OTHER +/-" at 12433.46,4379.13 h60
  text "COPPER THICKNESS (FINISHED):" at 11332.46,4243.64 h60
  text "1.4MIL (1oz)" at 12212.46,4090.92 h60
  text "2MIL (1.4oz)" at 12979.46,4090.92 h60
  text "2.8MIL (2oz)" at 13706.46,4090.92 h60
  text "OUTER:" at 11689.46,4086.64 h60
  text "X" at 13580,4080 h60
  text "1.4MIL (1oz)" at 12212.46,3933.92 h60
  text "2.8MIL (2oz)" at 12979.46,3933.92 h60
  text "N/A" at 13706,3934.29 h60
  text "INNER SIGNAL:" at 11400.38,3929.64 h60
  text "X" at 13580,3930 h60
  text "DRILLING:" at 11332.46,3790.64 h60
  text "REFERENCE:" at 11407.23,3673.64 h60
  text "X" at 12055.46,3673.64 h60
  text "AS SHOWN" at 12242.46,3673.64 h60
  text "X" at 12956.46,3673.64 h60
  text "NC_DRILL FILES" at 13093.46,3673.64 h60
  text "PTH MIN COPPER THICKNESS:" at 11407.23,3515.64 h60
  text "X" at 12757.46,3515.64 h60
  text "1MIL" at 12894.46,3515.64 h60
  text "OTHER" at 13391.46,3515.64 h60
  text "BOARD FINISH:" at 11332.46,3356.64 h60
  text "SILKSCREEN:" at 11487.68,3238.64 h60
  text "X" at 12436.46,3238.64 h60
  text "TOP" at 12562.46,3238.64 h60
  text "X" at 12946.46,3238.64 h60
  text "BOTTOM" at 13073.46,3238.64 h60
  text "SILKSCREEN COLOR:" at 11487.68,3071.64 h60
  text "X" at 12435.42,3071.64 h60
  text "WHITE" at 12562.46,3071.64 h60
  text "OTHER" at 13073.46,3071.64 h60
  text "SOLDER RESIST COLOR:" at 11487.68,2901.64 h60
  text "GREEN" at 12182.46,2742.44 h60
  text "BLUE" at 12773.46,2742.44 h60
  text "OTHER" at 13311.46,2742.44 h60
  text "X" at 13160,2740 h60
  text "RED" at 13860,2740 h60
  text "IMMERSION GOLD (ENIG)" at 12393.46,2553.92 h60
  text "ENEPIG" at 13731,2550.64 h60
  text "SURFACE FINISH:" at 11332.46,2549.64 h60
  text "IMM. TIN/SILVER OR EQUIV" at 11662,2392.64 h60
  text "OTHER" at 13093.46,2392.64 h60
  text "X" at 11500,2390 h60
  text "ARRAY/PANEL:" at 11332.46,2213.64 h60
  text "CUT AND TRIM PER MECH LAYER 1" at 12393.46,2209.35 h60
  text "N.C. ROUTE" at 12393.46,2057.64 h60
  text "X" at 13072.46,2057.64 h60
  text "V. SCORE" at 13259.46,2057.64 h60
  text "CERTIFICATION:" at 11332.46,1920.64 h60
  text "MATERIALS AND WORKMANSHIP FOR ALL PCBS" at 12057.46,1920.64 h60
  text "TO MEET OR EXCEED THE REQUIREMENTS OF:" at 12057.46,1822.64 h60
  text "X" at 11683.96,1686.13 h60
  text "ANSI IPC-A-600F CLASS ->" at 11822.96,1686.13 h60
  text "X" at 13462.02,1686.13 h60
  text "2" at 13580.96,1686.14 h60
  text "1" at 13265.96,1684.64 h60
  text "3" at 13934.96,1684.64 h60
  text "X" at 11686.02,1526.64 h60
  text "UL 94V-0" at 11822.96,1526.64 h60
  text "X" at 12498.02,1526.64 h60
  text "RoHS" at 12634.96,1526.64 h60
  text "OTHER" at 13279.36,1526.64 h60
  text "PER ORDER" at 13676.42,1526.64 h60
  text "ADDITIONAL REQUIREMENTS:" at 11332.46,1385.64 h60
  text "MICROSECTION:" at 11407.23,1270.64 h60
  text "YES" at 12312.96,1270.64 h60
  text "REQUIRED" at 13174.46,1114.49 h60
  text "BARE BOARD ELEC. TEST:" at 11407.23,1111.64 h60
  text "NONE" at 12712.96,1111.64 h60
  text "PER ORDER" at 13766.46,1111.64 h60
  text "X" at 13640,1110 h60
  text "MANUFACTURER'S UL:" at 11407.23,954.64 h60
  text "RAIL" at 12572.96,950.35 h60
  text "METAL" at 13064.77,950.35 h60
  text "X" at 13440,950 h60
  text "SILK" at 13576.46,950.35 h60
  text ".Layer_Name" at 577,-858.49 h60
M11 Gerber Information:
  lines w10: -292,-930.17 6308,-930.17 ; -292,-726.83 6310,-726.83 ; -292,-523.5 -292,-1133.5 3713,-1133.5 6310,-1133.5 6310,-523.5 -291.5,-523.5 -291.5,-1133.5 1284,-1133.5 ; 2173,-1133.5 2173,-523.5 ; 3440,-726.83 3440,-523.5 ; 4280,-726.83 4280,-523.5 ; 4902,-1140 4902,-937.17
  text "ALL ARTWORK VIEWED FROM TOP SIDE" at -228.5,-655.67 h60
  text "BOARD #:" at 2248,-655.67 h60
  text ".PRJ_Number" at 2793.5,-655.67 h60
  text "REV:" at 3638,-655.67 h60
  text ".PCB_Rev" at 3929.5,-655.67 h60
  text "SVN REV:" at 4476,-655.67 h60
  text ".VersionControl_RevNumber" at 4982,-655.67 h60
  text "LAYER NAME =" at -228.5,-858.49 h60
  text "PLOT NAME =" at -228.5,-1064.34 h60
  text ".plot_File_Name" at 577,-1064.34 h60
  text "GENERATED    :" at 2250,-1064.34 h60
  text ".Print_Date" at 3119.5,-1064.34 h60
  text ".Print_Time" at 3848.5,-1064.34 h60
  text "TEXAS INSTRUMENTS" at 5113,-1064.34 h60
M12 Stackup:
  lines w6: 11360,7460 13910,7460 ; 11360,7564.4 13910,7564.4 ; 11300,6975 ccw(c11334,6975) 11334,6941 13936,6941 ccw(c13936,6975) 13970,6975 13970,7681 ccw(c13936,7681) 13936,7715 11334,7715 ccw(c11334,7681) 11300,7681 11300,6975
  text "The Stackup Legend below this is static." at 11605.5,7874.5 h60
  text "If you change the stackup, update the Legend." at 11615.5,7784.5 h60
  text "Layer Stack Up Detail for: Ref_Design.PcbDoc" at 11360,7597.1 h57
  text "Layer" at 11360,7525.4 h24
  text "Gerber" at 12255.81,7525.4 h24
  text "Copper" at 12819.33,7525.4 h24
  text "Dielectric" at 13422.04,7525.4 h24
  text "Name" at 11360,7477.4 h24
  text "Document" at 12255.81,7477.4 h24
  text "Thickness" at 12819.33,7477.4 h24
  text "Material" at 13422.04,7477.4 h24
  text "Top Solder Mask" at 11360,7384.44 h34
  text "(.GTS)" at 12255.81,7384.44 h34
  text "Solder Resist" at 13422.04,7384.44 h34
  text "Top Layer" at 11360,7287.69 h34
  text "(.GTL)" at 12255.81,7287.69 h34
  text "1.4mil" at 12819.33,7287.69 h34
  text "FR-4" at 13422.04,7239.31 h34
  text "Bottom Layer" at 11360,7190.94 h34
  text "(.GBL)" at 12255.81,7190.94 h34
  text "1.4mil" at 12819.33,7190.94 h34
  text "Bottom Solder Mask" at 11360,7094.19 h34
  text "(.GBS)" at 12255.81,7094.19 h34
  text "Solder Resist" at 13422.04,7094.19 h34
  text ".Layer_Name" at 577,-858.49 h60
M13 Component Bodies Top:
  lines w5: 777.72,1335.03 777.72,1380
  text ".Layer_Name" at 577,-858.49 h60
M14 Component Bodies Bottom:
  text ".Layer_Name" at 577,-858.49 h60
M15 Courtyards Top:
  text ".Layer_Name" at 577,-858.49 h60
M16 Courtyards Bottom:
  text ".Layer_Name" at 577,-858.49 h60
Drill Drawing:
  lines w7: -90,2838.5 2110,2838.5 ; -90,2968.5 2110,2968.5 ; -150,1897 ccw(c-108,1897) -108,1855 2128,1855 ccw(c2128,1897) 2170,1897 2170,3283 ccw(c2128,3283) 2128,3325 -108,3325 ccw(c-108,3283) -150,3283 -150,1897
  text "Layer Stack Up Detail for: BOOST-DRV8711.PcbDoc" at -90,3113.45 h46
  text "Layer" at -90,2920 h30
  text "Gerber" at 699.1,2920 h30
  text "Copper" at 1082.34,2920 h30
  text "Dielectric" at 1514.55,2920 h30
  text "Name" at -90,2860 h30
  text "Document" at 699.1,2860 h30
  text "Thickness" at 1082.34,2860 h30
  text "Material" at 1514.55,2860 h30
  text "Top Solder Mask" at -90,2737.5 h42
  text "(.GTS)" at 699.1,2737.5 h42
  text "Solder Resist" at 1514.55,2737.5 h42
  text "Top Layer" at -90,2542.5 h42
  text "(.GTL)" at 699.1,2542.5 h42
  text "2.8mil" at 1082.34,2542.5 h42
  text "FR-4" at 1514.55,2445 h42
  text "Bottom Layer" at -90,2347.5 h42
  text "(.GBL)" at 699.1,2347.5 h42
  text "2.8mil" at 1082.34,2347.5 h42
  text "Bottom Solder Mask" at -90,2152.5 h42
  text "(.GBS)" at 699.1,2152.5 h42
  text "Solder Resist" at 1514.55,2152.5 h42
  text "*Special Note: RED Solder Resist, TI BoosterPack" at -80,1980 h42
  text ".legend" at 2302.5,785.5 h60
  text "Drill Table" at 2327.5,600.5 h60
  text ".Layer_Name" at 577,-858.49 h60

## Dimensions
0,0 to 0,1750 on M2 Board Dimensions
0,0 to 2000,0 on M2 Board Dimensions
